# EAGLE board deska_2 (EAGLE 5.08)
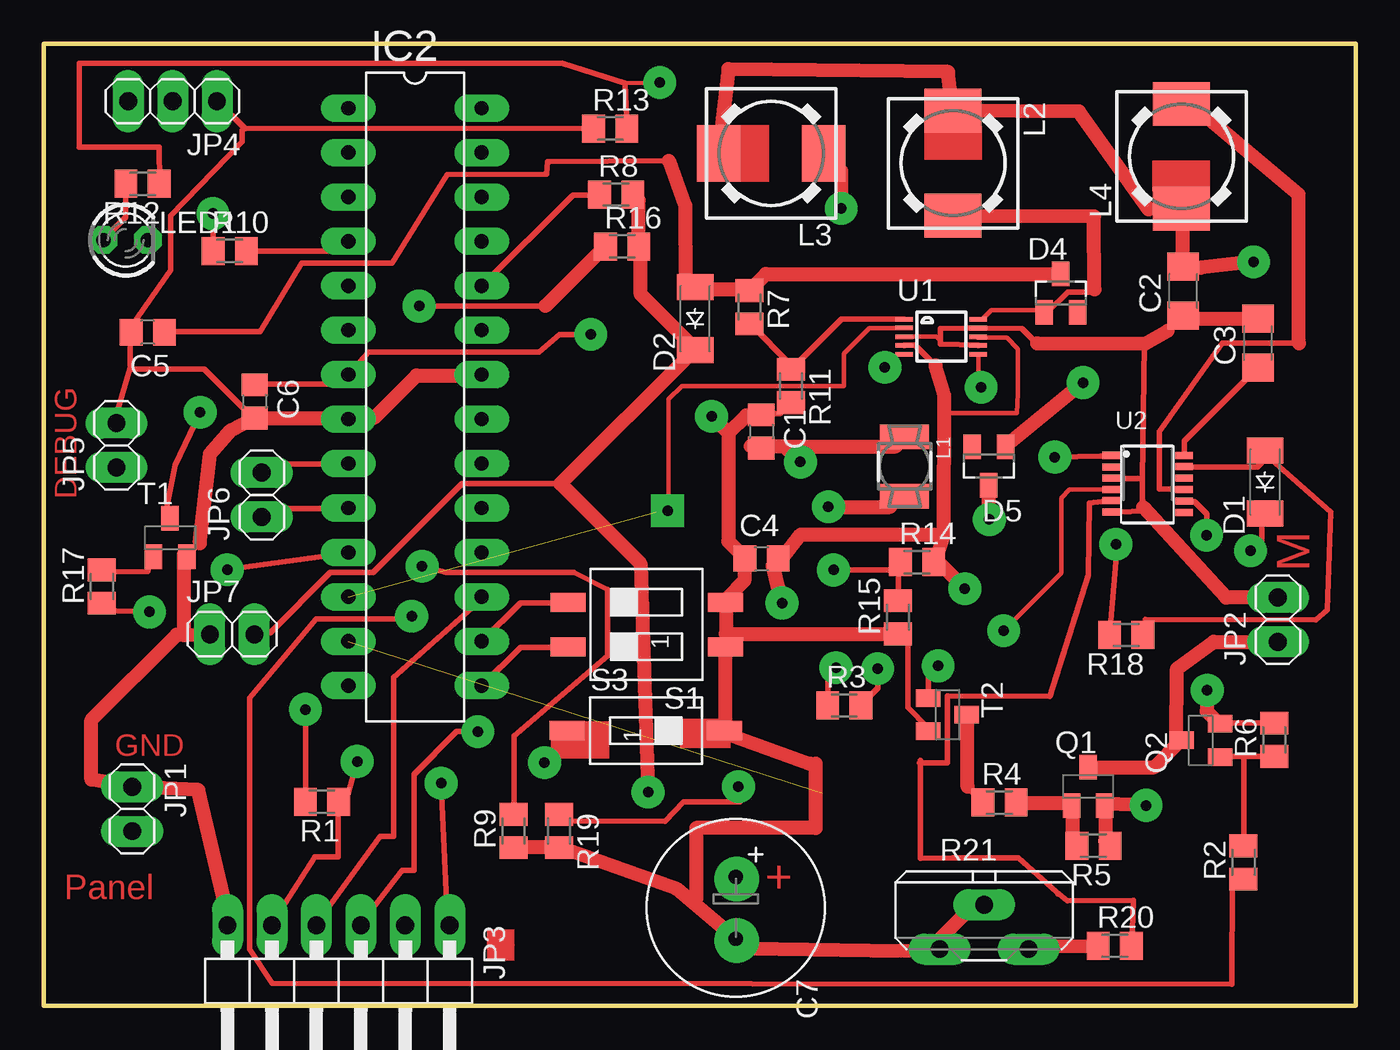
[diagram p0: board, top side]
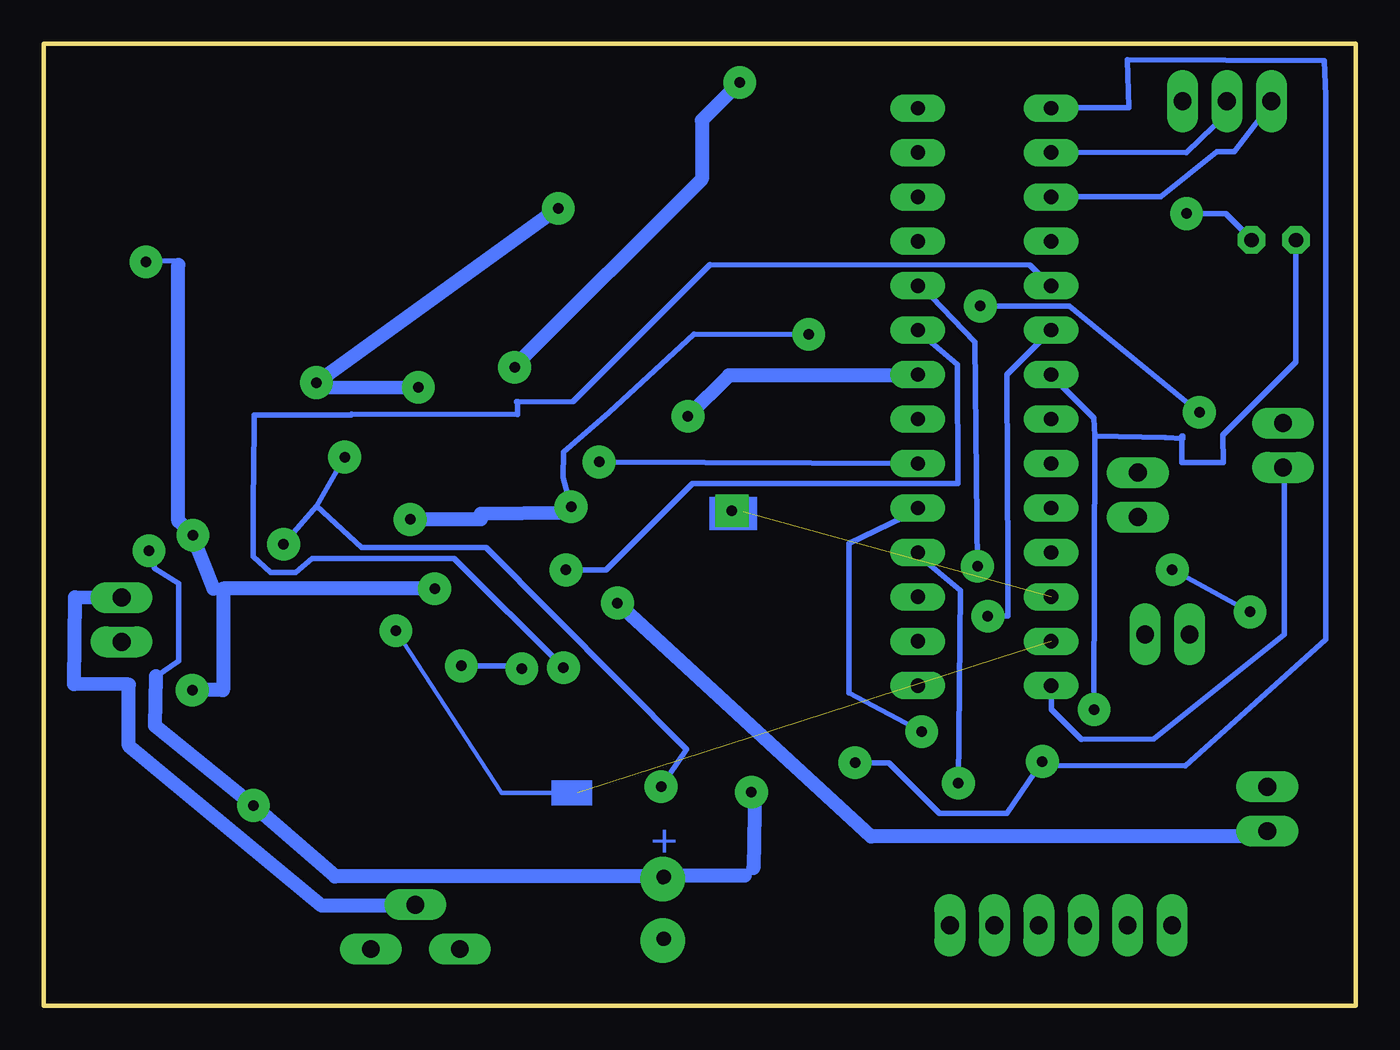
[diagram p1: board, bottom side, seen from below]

Size 75 x 55 mm. Coordinates in mm from the lower left corner, seen from the top.
Outline: 0,0 75,0 75,55 0,55 0,0
Copper layers (1*2+3*16): Top 0.035mm / dielectric 1.5mm / Route2 0.035mm / dielectric 0.15mm / Route3 0.035mm / dielectric 0.2mm / Bottom 0.035mm
Design rules "Trida_4_opi2 *": minimum track width 12mil, minimum drill 0.6mm, track to track 12mil, track to pad 8mil, pad to pad 8mil, via to via 20mil, smd to smd 12mil, copper to edge 25mil, drill to drill 12mil, minimum pad ring 15mil, minimum via ring 25mil, stop-mask expansion 4mil, vias tented up to drill 0mil, thermal gap 10mil
vRestrict: area 60.4,27.5 to 65.4,32.3; area 48.7,36.7 to 54.1,40.1; area 39,45.9 to 44.7,51.9; area 50.1,44.4 to 56.3,51.1; area 61.8,44.7 to 68.6,52.2

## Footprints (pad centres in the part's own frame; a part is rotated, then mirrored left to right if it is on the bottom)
C0805 = smd 1.3 x 1.5: 1 -0.95,0; 2 0.95,0
C1206 = smd 1.6 x 1.8: 1 -1.4,0; 2 1.4,0
E3,5-10 = drill 0.813 pad 1.6 round: + -1.778,0 | drill 0.813 pad 1.6 octagon: - 1.778,0
SOD-123_MINI-SMA = smd 1.5 x 2.1: A 1.8,0; C -1.8,0
SOT23 = smd 1 x 1.4: 1 -0.95,-1.1; 2 0.95,-1.1; 3 0,1.1
DIL28-3 = drill 0.813 long: 1 -16.51,-3.81; 2 -13.97,-3.81; 3 -11.43,-3.81; 4 -8.89,-3.81; 5 -6.35,-3.81; 6 -3.81,-3.81; 7 -1.27,-3.81; 8 1.27,-3.81; 9 3.81,-3.81; 10 6.35,-3.81; 11 8.89,-3.81; 12 11.43,-3.81; 13 13.97,-3.81; 14 16.51,-3.81; 15 16.51,3.81; 16 13.97,3.81; 17 11.43,3.81; 18 8.89,3.81; 19 6.35,3.81; 20 3.81,3.81; 21 1.27,3.81; 22 -1.27,3.81; 23 -3.81,3.81; 24 -6.35,3.81; 25 -8.89,3.81; 26 -11.43,3.81; 27 -13.97,3.81; 28 -16.51,3.81
1X02 = drill 1.016 long: 1 -1.27,0; 2 1.27,0
1X06/90 = drill 1.016 long: 1 -6.35,-3.81; 2 -3.81,-3.81; 3 -1.27,-3.81; 4 1.27,-3.81; 5 3.81,-3.81; 6 6.35,-3.81
1X03 = drill 1.016 long: 1 -2.54,0; 2 0,0; 3 2.54,0
MS50 = smd 2.8 x 1.4: 1 0,-1.7; 2 0,1.7
DR74 = smd 2.5 x 3.25: 1 -3,0; 2 3,0
LED3MM = drill 0.813 octagon: A -1.27,0; K 1.27,0
SOT23-BEC = smd 1 x 1.4: B -0.95,-1.1; C 0,1.1; E 0.95,-1.1
M0805 = smd 1.3 x 1.6: 1 -0.95,0; 2 0.95,0
PT-10S = drill 1.016 long: A -2.54,-1.27; E 2.54,-1.27; S 0,1.27
SMS-002 = smd 1.092 x 2.007: 1 -1.27,-4.496; 2 1.27,-4.496; 3 1.27,4.496; 4 -1.27,4.496
SMS-001 = smd 1.092 x 2.007: 1 0,-4.496; 2 0,4.496
MSOP10 = smd 0.25 x 1: 1 -1,-2.113; 2 -0.5,-2.113; 3 0,-2.113; 4 0.5,-2.113; 5 1,-2.113; 6 1,2.113; 7 0.5,2.113; 8 0,2.113; 9 -0.5,2.113; 10 -1,2.113
MSOP12 = smd 0.406 x 1: 1 -1.092,-2.098; 2 -0.429,-2.099; 3 0.215,-2.099; 4 0.871,-2.099; 5 1.503,-2.099; 6 2.158,-2.099; 7 2.182,2.083; 8 1.526,2.083; 9 0.87,2.083; 10 0.215,2.083; 11 -0.441,2.083; 12 -1.074,2.082

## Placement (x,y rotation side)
C1  100n  [C0805]  41.02,32.83 270 top
C2  10uF  [C1206]  65.14,40.87 90 top
C3  1uF  [C1206]  69.41,37.88 90 top
C4  100n  [C0805]  41.03,25.57 0 top
C5  100n  [C0805]  5.94,38.51 180 top
C6  100n  [C0805]  12.05,34.56 270 top
C7  10G / 16V  [E3,5-10]  39.56,5.6 270 top
D1  CGRM4001-G  [SOD-123_MINI-SMA]  69.81,29.95 90 top
D2  CGRM4001-G  [SOD-123_MINI-SMA]  37.24,39.28 90 top
D4  BAT54  [SOT23]  58.14,40.74 0 top
D5  BAT54  [SOT23]  54.03,30.85 180 top
IC2  ATMEGA168-PU  [DIL28-3]  21.22,34.81 270 top
JP1  [1X02]  5.05,11.25 270 top
JP2  [1X02]  70.55,22.07 90 top
JP3  [1X06/90]  16.85,0.79 180 top
JP4  [1X03]  7.37,51.71 180 top
JP5  [1X02]  4.15,32.04 90 top
JP6  [1X02]  12.46,29.21 90 top
JP7  [1X02]  10.77,21.23 0 top
L1  10uH  [MS50]  49.21,30.84 180 top
L2  100uH  [DR74]  51.98,48.17 270 top
L3  10uH  [DR74]  41.58,48.73 180 top
L4  10uH  [DR74]  65.04,48.55 90 top
LED1  [LED3MM]  4.69,43.78 0 top
Q1  BC807-40  [SOT23-BEC]  59.7,12.53 0 top
Q2  BC807-40  [SOT23-BEC]  66.13,15.18 90 top
R1  15k  [M0805]  15.9,11.67 180 top
R2  480  [M0805]  68.58,8.19 90 top
R3  560  [M0805]  45.76,17.17 0 top
R4  3k3  [M0805]  54.64,11.62 0 top
R5  4k7  [M0805]  60.01,9.16 180 top
R6  560R  [M0805]  70.35,15.2 90 top
R7  2M8  [M0805]  40.34,39.94 270 top
R8  180k  [M0805]  32.72,46.37 0 top
R9  15k  [M0805]  26.86,9.99 90 top
R10  330  [M0805]  10.63,43.15 0 top
R11  320k  [M0805]  42.71,35.43 270 top
R12  660k  [M0805]  5.65,46.99 180 top
R13  640k  [M0805]  32.38,50.15 0 top
R14  180k  [M0805]  49.92,25.36 0 top
R15  68k  [M0805]  48.83,22.21 90 top
R16  150R  [M0805]  33.07,43.41 0 top
R17  1k  [M0805]  3.33,23.96 90 top
R18  1M3  [M0805]  61.87,21.2 180 top
R19  330k  [M0805]  29.45,9.99 270 top
R20  100k  [M0805]  61.23,3.43 0 top
R21  56k  [PT-10S]  53.76,4.51 0 top
S1  SWS002  [SMS-002]  34.47,21.79 90 top
S3  SWS001  [SMS-001]  34.42,15.74 270 top
T1  BC817-40  [SOT23-BEC]  7.23,26.76 0 top
T2  BC817-40  [SOT23-BEC]  51.66,16.64 270 top
U1  LT1944  [MSOP10]  51.31,38.25 270 top
U2  LTC3105  [MSOP12]  63.11,30.38 270 top

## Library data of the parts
C1-C6 = rcl
C7 R1-R20 = resistor
D1 D2 D4 D5 = diode
IC2 = Arduino-AVR
JP1-JP7 = pinhead
L1 = inductor-neosid
L2-L4 = inductors
LED1 = led
Q1 Q2 T1 T2 = transistor
R21 = pot
S1 S3 = smd-special
U1 = opi1
U2 = opi2

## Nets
+3V3: C2.2 C4.2 JP1.2 L2.1 L3.2 L4.1 Q2.E R6.2 R14.2 U1.4 U1.8 U2.8
+4.1V: C6.1 D5.3 IC2.7 L1.2 LED1.A R1.2 R12.2
+15V: C7.+ D1.C D2.C JP7.2 Q1.E R5.1 R8.2 R16.2
GND: C1.1 C2.1 C3.2 C4.1 C5.2 C6.2 C7.- IC2.8 IC2.22 JP1.1 JP2.2 JP3.6 JP4.1 JP5.2 JP7.1 R9.1 R11.2 R13.1 R15.1 R19.2 R21.A R21.S S1.1 S1.2 S3.2 T1.E T2.E U1.3 U1.7 U1.9 U2.3 U2.6
N$1: IC2.1 JP3.5 R1.1 S3.1
N$3: IC2.5 R3.1
N$4: IC2.18 JP3.1
N$5: R4.1 T2.C
N$6: Q1.B R4.2 R5.2
N$7: JP2.1 Q1.C Q2.C
N$8: IC2.19 JP3.3
N$9: R3.2 T2.B
N$10: Q2.B R2.2 R6.1
N$11: D4.1 L2.2 U1.10
N$12: R18.2 R19.1 U2.1
N$13: IC2.6 R2.1
N$14: LED1.K R10.1
N$15: IC2.17 JP3.4
N$16: C1.2 IC2.20 L1.1
N$17: IC2.3 JP4.3
N$18: IC2.2 JP4.2
N$19: IC2.4 R10.2
N$20: IC2.24 R8.1 R9.2
N$21: R7.2 R11.1 U1.1
N$22: C3.1 U2.12
N$23: IC2.23 R14.1 R15.2
N$24: D5.1 L3.1 U1.6
N$25: R16.1 T1.C
N$26: R12.1 R13.2 U1.5
N$27: R17.2 T1.B
N$28: IC2.11 R17.1
N$29: L4.2 U2.9
N$31: R20.2 U2.5
N$32: R20.1 R21.E
N$34: D1.A R18.1 U2.11
N$35: C5.1 D2.A D4.3 R7.1
N$36: IC2.14 JP5.1
N$37: IC2.16 S1.3
N$38: IC2.15 S1.4
N$41: IC2.10 JP6.1
N$42: IC2.9 JP6.2
SHDN: IC2.12 U1.2
SHDN2: IC2.13 U2.4

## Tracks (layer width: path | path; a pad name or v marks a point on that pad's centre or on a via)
+3V3  (via drill 0.6)
  Top 0.254: U1.8 53.4,38.25 53.34,38.19 55.05,38.19 55.69,37.55 55.69,34.99 55.64,33.88 51.44,33.9 51.47,34.91
  Top 0.305: 65.1,45.49 L4.1 64.9,45.59 63.14,45.54 | 65.1,42.29 C2.2 65.25,42.19 66.12,42.19 | 38.58,48.74 L3.2 | L2.1 51.94,51.13 | v66.47,26.9 66.47,28.12 65.76,28.83 65.2,28.83 U2.8 | 67.18,16.13 Q2.E 67.33,16.18 70.33,16.18 R6.2 | 50.98,36.6 49.81,37.77 49.2,37.77 U1.4 | 50.98,25.48 50.88,25.38 R14.2 51.08,25.43 | 42.19,25.58 C4.2 41.94,25.43 41.68,25.17
  Top 0.813: 65.1,42.29 65.1,45.49 | 38.58,48.74 39.14,53.54 51.69,53.39 51.94,51.13 | 63.14,45.54 59.18,51.12 L2.1 | v66.51,18.05 66.47,16.84 67.18,16.13 | 51.45,26.95 50.98,25.48 | 51.45,26.95 51.47,34.91 50.98,36.6 | 42.19,25.58 43.27,26.94 51.45,26.95 | v42.2,23.02 41.68,25.17 | 51.08,25.43 v52.65,23.85 | v69.15,42.53 66.12,42.19
  Bottom 0.305: 65.29,23.85 64.75,23.85 | 64.75,18.05 64.78,18.05 | JP1.2 4.86,9.68 | 67.28,27.71 67.31,27.71 | 67.31,42.37 67.33,42.37 67.33,42.61 v69.15,42.53
  Bottom 0.813: 64.75,18.05 64.75,23.85 v52.65,23.85 | 64.78,18.05 v66.51,18.05 | 65.29,23.85 v66.47,26.9 67.28,27.71 | 4.86,9.68 27.71,9.68 v42.2,23.02 | 67.31,27.71 67.31,42.37
+4.1V  (via drill 0.6)
  Top 0.305: 48.37,28.52 L1.2 | 54.03,29.34 D5.3 | R12.2 4.7,46.97 4.7,45.09 3.43,43.81 LED1.A | C6.1 12.06,35.53 16.89,35.53 17.4,36.04 IC2.7 17.5,36.2 18.58,37.36 28.31,37.36 29.48,38.38 v31.27,38.38 | v14.96,16.94 14.96,11.71 R1.2
  Top 0.813: v54.05,27.8 54.03,29.34 | v44.86,28.52 48.37,28.52
  Bottom 0.305: 45.21,28.17 v44.86,28.52 45.31,30.21 45.28,31.65 42.7,33.91 42.67,33.91 37.83,38.39 v31.27,38.38 | 14.92,32.56 14.96,33.6 17.4,36.04 IC2.7 | v14.96,16.94 14.92,32.56 | LED1.A 3.43,43.76 3.43,36.8 7.59,32.64 7.57,31.05 9.94,31.05 9.94,32.56 9.89,32.56 9.89,32.42 10.9,32.5 14.92,32.56
  Bottom 0.813: 45.21,28.17 50.01,28.12 50.01,27.8 v54.05,27.8
+15V  (via drill 0.6)
  Top 0.305: 60.68,9.42 60.94,9.17 R5.1 | 60.68,11.4 Q1.E 60.73,11.56 | v68.99,26.01 69.62,26.34 69.62,27.46 D1.C | 34.01,46.05 33.71,46.35 R8.2 | R16.2 34.11,43.31 | 37.21,37.52 D2.C 37.11,37.41 | 29.54,29.84 23.9,29.84 18.82,24.77 16.38,24.77 12.93,21.31 JP7.2
  Top 0.813: 60.68,11.4 60.68,9.42 | v63.02,11.46 60.73,11.56 | R16.2 34.01,46.05 | 37.21,37.52 37.22,37.58 34.12,40.68 34.11,43.31 | 37.11,37.41 29.54,29.84 34.11,25.27 v34.54,12.22
  Bottom 0.305: v68.99,26.01 68.67,25.01 67.3,24.13 67.28,19.71 68.58,18.83 | 39.6,7.39 C7.+ 39.45,7.44 | 34.92,7.44 34.82,7.34 34.43,7.86 | v34.54,12.22 34.35,12.61
  Bottom 0.813: 68.58,18.83 68.63,16 v63.02,11.46 58.34,7.39 39.6,7.39 | 34.92,7.44 39.45,7.44 | 34.35,12.61 34.43,7.86
GND  (via drill 0.6)
  Top 0.254: U1.3 51.04,38.25 51.26,38.03
  Top 0.305: 8.03,21.18 7.7,21.31 JP7.1 | 8.03,25.81 T1.E 8.93,26.43 | 10.49,5.31 JP3.6 | 11.51,50.14 31.42,50.16 R13.1 | 11.51,50.14 JP4.1 | 4.95,36.5 4.95,38.48 C5.2 5.19,39.1 7.26,42.06 7.26,45.16 11.35,49.4 11.35,50.06 11.51,50.14 | 4.95,36.5 4.09,33.57 JP5.2 | 12.06,33.6 C6.2 11.91,33.66 9.17,36.4 5.05,36.4 4.95,36.5 | 17.35,33.6 IC2.8 18.87,33.6 | 25.02,36.04 IC2.22 | 62.81,29.11 62.8,30.14 61.54,30.15 | 62.81,29.11 62.79,28.3 61.54,28.22 61.04,28.22 U2.6 | 61.54,30.15 61.04,30.15 U2.3 | U1.7 53.42,37.77 51.26,37.82 51.26,38.03 51.27,38.72 52.76,38.73 53.42,38.73 U1.9 53.57,38.73 55.91,38.71 56.78,37.86 | 64.24,38.58 65.1,39.45 C2.1 65.15,39.29 | 61.54,30.15 62.79,30.11 62.93,37.83 | 69.37,39.29 C3.2 | 62.85,28.51 62.81,29.11 | T2.E 50.52,15.72 50.52,15.93 49.4,17.04 49.4,20.7 48.84,21.26 R15.1 48.69,21.26 | 38.94,15.77 S3.2 38.84,15.62 | 38.94,20.5 S1.1 38.99,20.65 38.99,21.26 | R11.2 42.7,34.47 42.09,33.86 40.26,33.86 C1.1 40.16,33.76 | 38.99,23.24 38.99,23.09 S1.2 38.99,22.94 | 40.06,25.53 C4.1 40.01,25.68 | R21.A 50.39,3.01 | 52.93,5.55 R21.S | 26.9,9.07 R9.1 | 29.44,9.07 R19.2 29.59,9.02 | 40.21,3.28 39.7,3.79 C7.-
  Top 0.813: 8.03,21.18 8.03,25.81 | JP7.1 7.59,21.21 2.72,16.33 2.72,12.93 JP1.1 8.84,12.33 10.49,5.31 | 12.06,33.6 17.35,33.6 | 25.02,36.04 21.31,36.04 18.87,33.6 | 8.93,26.43 9.51,31.55 10.69,32.89 C6.2 | 64.24,38.58 62.93,37.83 56.78,37.86 | 65.15,39.29 69.37,39.29 | 62.85,28.51 67.59,23.34 JP2.2 | 38.94,20.5 38.94,15.77 | 40.06,25.53 40.06,24.31 38.99,23.24 | 39.14,32.74 40.16,33.76 | 39.14,32.74 39.14,26.54 40.01,25.68 | 38.99,22.94 38.99,21.26 48.69,21.26 | 50.39,3.01 52.93,5.55 | 29.44,9.07 26.9,9.07 | 36.2,6.68 29.59,9.02 | 36.2,6.68 C7.- | 40.21,3.28 49.01,3.15 R21.A | 38.84,15.62 43.8,13.83 44.12,13.83 44.12,10.16 37.3,10.16 37.3,6.13 37.01,6.13 37.01,5.99 36.2,6.68 | v38.18,33.71 39.14,32.74
  Bottom 0.305: 70.43,23.34 JP2.2 | R21.S 53.19,5.71 | IC2.22 25.07,36.04
  Bottom 0.813: 70.43,23.34 73.2,23.37 73.27,18.39 70.14,18.36 70.14,14.86 59.11,5.71 53.19,5.71 | 25.07,36.04 35.84,36.04 v38.18,33.71
N$1  (via drill 0.6)
  Top 0.305: JP3.5 13.08,4.6 13.08,4.75 15.49,8.48 15.49,8.51 16.84,8.51 R1.1 16.99,11.71 17.4,12.12 v17.92,13.97 | v28.63,13.89 29.9,15.16 29.9,15.72 S3.1
  Bottom 0.305: v28.63,13.89 26.7,13.89 23.8,11 19.94,11 v17.92,13.97 17.98,13.74 9.75,13.7 1.71,20.94 1.71,52.03 1.79,54.04 13.04,54.09 12.98,51.33 17.4,51.33 IC2.1
N$3  (via drill 0.6)
  Top 0.305: v45.29,19.33 44.83,18.87 44.83,17.2 R3.1
  Bottom 0.305: v45.29,19.33 51.54,25.58 59.66,25.58 60.6,24.77 62.03,24.77 63.02,25.68 63.02,28.73 62.98,33.03 62.98,33.78 57.43,33.78 57.39,33.83 47.9,33.81 47.92,34.56 47.98,34.56 47.98,34.51 44.74,34.54 36.92,42.37 18.62,42.34 17.45,41.17 IC2.5
N$4  (via drill 0.6)
  Top 0.305: v22.72,12.72 23.09,4.7 JP3.1
  Bottom 0.305: v22.72,12.72 22.61,23.74 25.02,25.78 25.02,25.88 IC2.18
N$5
  Top 0.305: 52.81,12.52 53.67,11.66 R4.1 | 52.81,16.64 T2.C
  Top 0.813: 52.81,12.52 52.81,16.64
N$6
  Top 0.305: 58.8,9.42 R5.2 | 58.8,11.4 Q1.B 58.6,11.46 58.45,11.61 | R4.2 55.6,11.61
  Top 0.813: 58.8,11.4 58.8,9.42 | 55.6,11.61 58.45,11.61
N$7
  Top 0.305: Q1.C 59.72,13.64 | 65,15.16 Q2.C 64.75,15.11
  Top 0.813: 59.72,13.64 63.48,13.64 65,15.16 | 64.75,15.11 64.78,19.27 66.88,20.8 JP2.1
N$8  (via drill 0.6)
  Top 0.305: v24.82,15.67 23.6,15.67 21.16,13.23 21.16,7.75 20.47,7.75 20.47,7.73 | 20.47,7.73 18.16,4.75 18.16,4.6 JP3.3 | 20.47,7.73 20.47,7.71
  Bottom 0.305: v24.82,15.67 28.97,17.89 28.97,26.43 25.07,28.32 25.07,28.42 IC2.19
N$9  (via drill 0.6)
  Top 0.305: v51.13,19.43 50.57,18.87 50.57,17.6 T2.B | v47.68,19.28 47.68,18.16 46.71,17.2 R3.2
  Bottom 0.305: v51.13,19.43 47.83,19.43 v47.68,19.28
N$10
  Top 0.305: 68.61,14.25 70.33,14.25 R6.1 | 68.61,14.25 67.23,14.25 Q2.B | R2.2 68.61,9.17 68.61,14.25
N$11
  Top 0.254: U1.10 53.65,39.25 54.17,39.76 57.07,39.76 D4.1
  Top 0.305: 60.07,40.97 60.12,40.78 59.91,40.79 58.53,40.79 57.38,39.65 57.23,39.65 D4.1 | 51.99,45.14 L2.2
  Top 0.813: 60.07,40.97 60.03,45.12 51.99,45.14
N$12  (via drill 0.6)
  Top 0.305: v57.8,31.37 60.43,31.42 60.98,31.42 U2.1 | v61.29,26.39 61.29,25.38 60.96,21.69 R18.2 | v39.71,12.52 40.03,12.33 40.03,11.96 39.8,11.96 39.8,11.67 36.58,11.67 35.51,10.55 29.52,10.58 R19.1
  Bottom 0.305: 59.41,28.57 v57.8,31.37 | 59.41,28.57 v61.29,26.39 | v39.71,12.52 38.27,14.67 49.71,26.19 56.82,26.19 59.41,28.57
N$13  (via drill 0.6)
  Top 0.305: v21.03,22.28 20.36,22.28 20.36,22.12 15.57,22.11 11.76,17.6 11.76,3.23 13.04,1.28 67.91,1.22 67.94,7.24 68.56,7.24 R2.1
  Bottom 0.305: v21.03,22.28 19.88,22.28 19.88,24.98 19.94,36.09 IC2.6
N$14  (via drill 0.6)
  Top 0.305: v9.68,45.29 R10.1
  Bottom 0.305: v9.68,45.29 7.44,45.29 5.97,43.81 LED1.K
N$15
  Top 0.305: IC2.17 25.02,23.34 25.02,23.24 20,18.77 20,9.68 19.24,9.68 19.24,9.69 15.62,4.75 15.62,4.6 JP3.4
N$16  (via drill 0.6)
  Top 0.305: 48.69,31.98 49.2,32.49 L1.1 | 40.42,31.98 C1.2
  Top 0.813: 42.34,31.98 48.69,31.98 | 42.34,31.98 40.42,31.98 | v43.26,31.09 42.34,31.98
  Bottom 0.305: v43.26,31.09 25.07,31.01 IC2.20
N$17
  Bottom 0.305: IC2.3 17.4,46.25 11.15,46.25 7.95,48.82 6.93,48.82 4.85,51.54 4.85,51.69 JP4.3
N$18
  Bottom 0.305: IC2.2 17.4,48.79 9.69,48.77 7.3,51.05 7.39,51.69 JP4.2
N$19
  Top 0.305: R10.2 16.89,43.16 17.4,43.66 IC2.4
N$20  (via drill 0.6)
  Top 0.305: v21.63,25.13 22.99,24.77 30.3,24.77 32.22,23.8 32.22,19.99 26.9,15.42 26.9,10.95 R9.2 | R8.1 31.73,46.35 30.25,46.35 25.07,41.17 IC2.24
  Bottom 0.305: v21.63,25.13 21.78,37.95 24.88,41.19 IC2.24
N$21
  Top 0.305: U1.1 49.15,39.24 45.59,39.24 42.75,36.4 R11.1 42.75,36.6 40.36,38.99 R7.2
N$22
  Top 0.305: U2.12 65.2,31.47 65.2,32.28 69.37,36.45 C3.1
N$23  (via drill 0.6)
  Top 0.305: R15.2 48.84,23.19 48.84,25.22 48.95,25.32 R14.1 48.74,24.92 v45.15,24.92
  Bottom 0.305: v45.15,24.92 42.85,24.92 37.92,29.84 23.75,29.84 22.73,29.86 22.76,36.65 25.02,38.58 IC2.23
N$24  (via drill 0.6)
  Top 0.254: U1.6 53.42,36.03 v53.58,35.36
  Top 0.305: 45.59,47.73 44.63,48.69 L3.1 | D5.1 54.94,31.98
  Top 0.813: 54.94,31.98 v59.41,35.62 | v45.59,45.59 45.59,47.73
  Bottom 0.254: 59.33,35.32 v59.41,35.62
  Bottom 0.813: v59.41,35.62 v45.59,45.59 | v53.58,35.36 59.33,35.32
N$25  (via drill 0.6)
  Top 0.305: v8.94,33.92 7.52,30.91 7,28.35 T1.C | v21.46,40.01 28.68,40.01 | 32.08,43.41 R16.1
  Top 0.813: 28.68,40.01 32.08,43.41
  Bottom 0.305: v8.94,33.92 16.38,40.01 v21.46,40.01
N$26  (via drill 0.6)
  Top 0.254: U1.5 48.84,37.25 v48.08,36.5 | v35.22,52.78 33.11,52.74 33.23,52.74
  Top 0.305: R12.1 6.63,47.02 6.6,49.09 2.03,49.1 2.02,53.87 29.64,53.87 33.23,52.74 33.35,50.16 R13.2
  Bottom 0.254: 48.08,36.56 v48.08,36.5
  Bottom 0.813: 48.08,36.56 37.38,47.27 37.38,50.62 v35.22,52.78
N$27
  Top 0.305: T1.B 6.16,25.6 5.94,24.83 3.25,24.8 R17.2
N$28  (via drill 0.6)
  Top 0.305: v6.04,22.52 3.29,22.59 R17.1 | v10.49,24.93 17.4,25.88 IC2.11
  Bottom 0.305: v6.04,22.52 v10.49,24.93
N$29
  Top 0.305: 71.75,37.88 67.36,37.88 63.77,32.84 63.77,29.54 65.15,29.54 U2.9 | 65.02,52.02 L4.2
  Top 0.813: 71.75,37.88 71.73,46.38 65.02,52.02
N$30  (via drill 0.6 pad 2.54)
  other vias: 39.61,7.25
N$31
  Top 0.305: 50.1,13.8 50.1,8.43 51.98,8.46 55.72,8.45 57.89,6.51 | 50.1,14.02 50.1,13.8 | 50.1,13.8 50.05,13.89 51.66,13.89 51.66,17.7 51.69,17.7 57.51,17.68 59.73,24.62 59.78,28.75 60.98,28.88 U2.5 | 57.89,6.51 58.51,5.99 62.28,6.02 62.2,3.43 R20.2 | 57.98,6.4 57.89,6.51
N$32
  Top 0.305: 55.77,3.39 55.51,3.14 R21.E
  Top 0.813: 55.77,3.39 R20.1
N$34
  Top 0.305: U2.11 65.2,30.81 69.37,30.81 69.62,31.06 D1.A 69.65,31.67 73.56,28.22 73.38,22.63 72.71,22.05 62.98,22.07 R18.1
N$35
  Top 0.305: D4.3 | 40.36,40.92 R7.1 40.21,40.97 | 35.74,48.31 28.79,48.26 28.74,47.55 23.05,47.52 19.91,42.46 14.73,42.44 12.37,38.53 6.93,38.53 C5.1 | 36.69,41.19 D2.A 37.31,40.97
  Top 0.813: D4.3 41.27,41.83 40.36,40.92 | 35.74,48.31 36.66,45.74 36.69,41.19 | 37.31,40.97 40.21,40.97
N$36
  Bottom 0.305: IC2.14 17.4,18.26 17.4,16.94 15.67,15.21 11.53,15.25 4.09,21.22 4.08,30.72 JP5.1
N$37
  Top 0.305: S1.3 29.95,23.04 27.25,23.04 25.07,20.85 IC2.16
N$38
  Top 0.305: S1.4 29.95,20.5 27.25,20.5 25.07,18.31 IC2.15
N$39  (via drill 0.6 pad 2.54)
  other vias: 39.61,3.73
N$41
  Top 0.305: IC2.10 17.4,28.42 13.34,28.42 12.78,27.86 JP6.1
N$42
  Top 0.305: IC2.9 17.4,30.96 13.34,30.96 12.78,30.4 JP6.2
SHDN  (via drill 0.6)  (1 unrouted)
  Top 0.254: U1.2 47.21,38.75 45.73,37.27 45.73,35.45 45.74,35.43 36.47,35.43 35.73,34.68 35.73,28.36 v35.66,28.3
  Bottom 0.254: v35.66,28.3 35.08,28.3 35.01,28.23
SHDN2  (via drill 0.6)  (1 unrouted)
  Top 0.254: U2.4 58.64,29.51 58.17,29.03 58.17,24.74 v54.86,21.44
  Bottom 0.254: v54.86,21.44 48.83,12.17 44.48,12.17
(copper drawn outside any net)
  shapes: Bottom area x2, Top area x5

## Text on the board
Top: DEBUG | M | GND | Panel | + | . | . | . | .
Bottom: +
